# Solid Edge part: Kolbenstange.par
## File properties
Username: bmolnar
Dokumentum tartalom típus: 0
Author: bmolnar
Last saved by: bmolnar
Revision: 81
Sűrűség: 0,000 kg/m^3
Pontosság: 0,990
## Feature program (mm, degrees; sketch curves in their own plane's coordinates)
base feature "unnamed BaseFeature 1"
sketch for "unnamed Protrusion 1" plane through (23.3, 0, 0) normal (1, 0, 0) x-axis (0, -1, 0)
  circle centre (0, 0) radius 10
extrude "unnamed Protrusion 1" add finite 6.7 along +normal
sketch for "Furat_1" plane through (-15, 0, 0) normal (-1, 0, 0) x-axis (0, 1, 0)
hole "Furat_1" diameter 6 finite  VBottomAngle = 118 deg; ThreadDepth = 15 mm
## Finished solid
Body 1: solid body, 14 faces, 20 edges, 8 vertices.
  Faces by surface: plane 7, cylinder 4, cone 2, torus 1
  Edges by curve: circle 10, line 6, ellipse 2, intersection 2
Bounding box of the edges (mm; curved faces can reach further): 45.000 x 20.000 x 20.000, from (-15, -10, -10) to (30, 10, 10).
Cylindrical faces by radius (mm): R2.4585 x2, R5 x1, R10 x1
Conical faces (half-angle, radius in mm at the cone's reference point): 45 deg R2.8085 x1, 59 deg R2.4585 x1
Toroidal faces (ring radius, tube radius in mm): R3.8 r1.2 x1
Planar faces by outward normal: +x 1, +z 1, -x 2, -z 1, oblique 2
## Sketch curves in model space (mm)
circle centre (23.3, 0, 0) radius 10
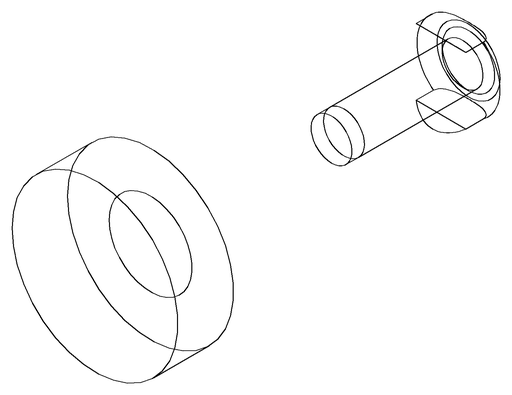
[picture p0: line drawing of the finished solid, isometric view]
